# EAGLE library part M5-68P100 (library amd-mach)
AMD MACH SERIES
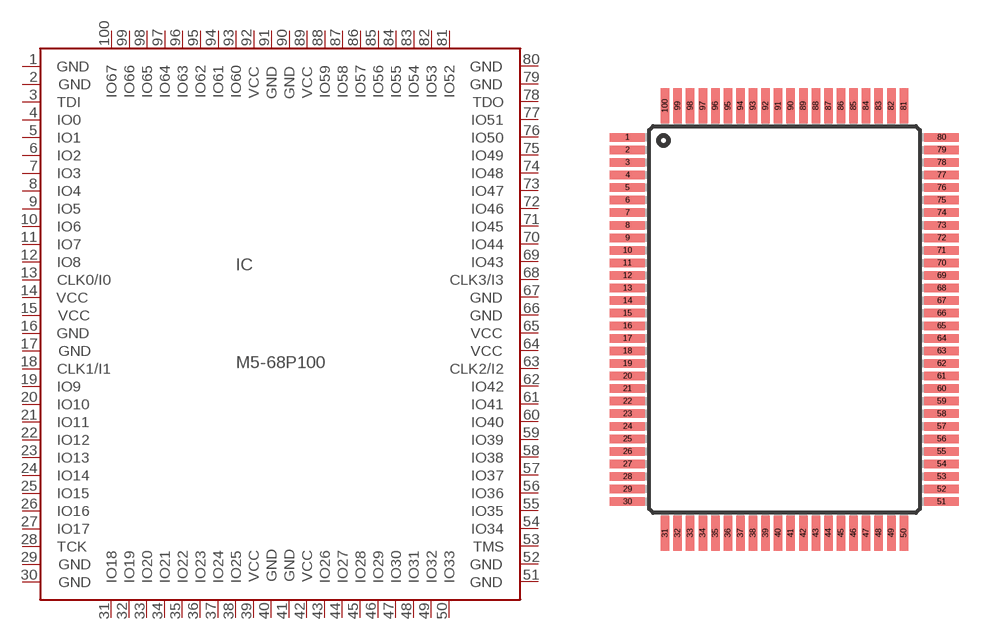
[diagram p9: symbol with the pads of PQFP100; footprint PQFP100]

Designator prefix IC

## M5-68P100 (OC_FARNELL: unknown; OC_NEWARK: unknown)  [PQFP100]
1  GND  pwr
2  GND  pwr
3  TDI  in
4  IO0
5  IO1
6  IO2
7  IO3
8  IO4
9  IO5
10  IO6
11  IO7
12  IO8
13  CLK0/I0  in
14  VCC  pwr
15  VCC  pwr
16  GND  pwr
17  GND  pwr
18  CLK1/I1  in
19  IO9
20  IO10
21  IO11
22  IO12
23  IO13
24  IO14
25  IO15
26  IO16
27  IO17
28  TCK  in
29  GND  pwr
30  GND  pwr
31  IO18
32  IO19
33  IO20
34  IO21
35  IO22
36  IO23
37  IO24
38  IO25
39  VCC  pwr
40  GND  pwr
41  GND  pwr
42  VCC  pwr
43  IO26
44  IO27
45  IO28
46  IO29
47  IO30
48  IO31
49  IO32
50  IO33
51  GND  pwr
52  GND  pwr
53  TMS  in
54  IO34
55  IO35
56  IO36
57  IO37
58  IO38
59  IO39
60  IO40
61  IO41
62  IO42
63  CLK2/I2  in
64  VCC  pwr
65  VCC  pwr
66  GND  pwr
67  GND  pwr
68  CLK3/I3  in
69  IO43
70  IO44
71  IO45
72  IO46
73  IO47
74  IO48
75  IO49
76  IO50
77  IO51
78  TDO  out
79  GND  pwr
80  GND  pwr
81  IO52
82  IO53
83  IO54
84  IO55
85  IO56
86  IO57
87  IO58
88  IO59
89  VCC  pwr
90  GND  pwr
91  GND  pwr
92  VCC  pwr
93  IO60
94  IO61
95  IO62
96  IO63
97  IO64
98  IO65
99  IO66
100  IO67

## Footprint PQFP100 (pad centres in mm)
PLASTIC QUAD FLAT PACK
smd 1.8 x 0.44: 1 -8.125,9.425; 2 -8.125,8.775; 3 -8.125,8.125; 4 -8.125,7.475; 5 -8.125,6.825; 6 -8.125,6.175; 7 -8.125,5.525; 8 -8.125,4.875; 9 -8.125,4.225; 10 -8.125,3.575; 11 -8.125,2.925; 12 -8.125,2.275; 13 -8.125,1.625; 14 -8.125,0.975; 15 -8.125,0.325; 16 -8.125,-0.325; 17 -8.125,-0.975; 18 -8.125,-1.625; 19 -8.125,-2.275; 20 -8.125,-2.925; 21 -8.125,-3.575; 22 -8.125,-4.225; 23 -8.125,-4.875; 24 -8.125,-5.525; 25 -8.125,-6.175; 26 -8.125,-6.825; 27 -8.125,-7.475; 28 -8.125,-8.125; 29 -8.125,-8.775; 30 -8.125,-9.425; 51 8.125,-9.425; 52 8.125,-8.775; 53 8.125,-8.125; 54 8.125,-7.475; 55 8.125,-6.825; 56 8.125,-6.175; 57 8.125,-5.525; 58 8.125,-4.875; 59 8.125,-4.225; 60 8.125,-3.575; 61 8.125,-2.925; 62 8.125,-2.275; 63 8.125,-1.625; 64 8.125,-0.975; 65 8.125,-0.325; 66 8.125,0.325; 67 8.125,0.975; 68 8.125,1.625; 69 8.125,2.275; 70 8.125,2.925; 71 8.125,3.575; 72 8.125,4.225; 73 8.125,4.875; 74 8.125,5.525; 75 8.125,6.175; 76 8.125,6.825; 77 8.125,7.475; 78 8.125,8.125; 79 8.125,8.775; 80 8.125,9.425
smd 0.44 x 1.8: 31 -6.175,-11.05; 32 -5.525,-11.05; 33 -4.875,-11.05; 34 -4.225,-11.05; 35 -3.575,-11.05; 36 -2.925,-11.05; 37 -2.275,-11.05; 38 -1.625,-11.05; 39 -0.975,-11.05; 40 -0.325,-11.05; 41 0.325,-11.05; 42 0.975,-11.05; 43 1.625,-11.05; 44 2.275,-11.05; 45 2.925,-11.05; 46 3.575,-11.05; 47 4.225,-11.05; 48 4.875,-11.05; 49 5.525,-11.05; 50 6.175,-11.05; 81 6.175,11.05; 82 5.525,11.05; 83 4.875,11.05; 84 4.225,11.05; 85 3.575,11.05; 86 2.925,11.05; 87 2.275,11.05; 88 1.625,11.05; 89 0.975,11.05; 90 0.325,11.05; 91 -0.325,11.05; 92 -0.975,11.05; 93 -1.625,11.05; 94 -2.275,11.05; 95 -2.925,11.05; 96 -3.575,11.05; 97 -4.225,11.05; 98 -4.875,11.05; 99 -5.525,11.05; 100 -6.175,11.05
